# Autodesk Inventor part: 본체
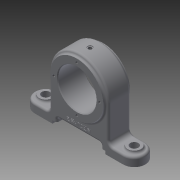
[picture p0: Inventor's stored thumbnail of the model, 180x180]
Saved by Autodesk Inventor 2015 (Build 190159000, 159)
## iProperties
Created: 2019-05
Part Number: 본체
Material: 알루미늄 6061
Document SubType Name: Modeling
Designer: now
Density: 2.7 g/cm^3
Appearance: 기본값
Mass: 455.028 g
Surface Area: 318.707 cm^2
Volume: 168.529 cm^3
Author: now
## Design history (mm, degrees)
sketch "스케치1"
  geometry: L1 (-75, 15)-(75, 15); L2 (75, 15)-(75, -15); L3 (75, -15)-(-75, -15); L4 (-75, -15)-(-75, 15); L5 (-75, 15)-(75, -15); L6 (75, 15)-(-75, -15); 1 further point
  constraints: 12 end point, 2 midpoint, 2 parallel, 1 horizontal, 1 perpendicular
  dimensions: "d0" = 150 distance of L2.end L3.end; "d1" = 30 distance of L1.end L2.end
extrude "돌출1" new body sketch "스케치1" distance "d2" = 12; taper "d3" = 0 deg
fillet "모깎기1" dims "d4" = 15
sketch "스케치2"
  geometry: L1 (120, 0)-(0, 0) reference; C1 r 40 at (60, 60); 2 further points
  constraints: 1 centre point, 1 midpoint, 1 vertical alignment
  dimensions: "d5" = 80 diameter of C1; "d6" = 60 distance of C1.centre point (60, 0)
extrude "돌출2" join sketch "스케치2" distance "d7" = 30; taper "d8" = 0 deg
sketch "스케치3"
  geometry: L1 (120, 0)-(0, 0) reference; L2 (0, 12)-(120, 12) reference; L3 (20, 12)-(100, 12); L4 (100, 12)-(100, 60); L5 (100, 60)-(20, 60); L6 (20, 60)-(20, 12); 3 further points
  constraints: 8 end point, 2 midpoint, 2 parallel, 1 horizontal, 1 perpendicular, 1 point on line, 1 vertical alignment
  dimensions: "d9" = 80 distance of L4.end L5.end; "d10" = 48 distance of L3.end L4.end
extrude "돌출3" join sketch "스케치3" distance "d11" = 30; taper "d12" = 0 deg
sketch "스케치4"
  geometry: A1 r 40 centre (60, 60) between (100, 60) and (20, 60) reference; 1 further point
hole "구멍1" sketch "스케치4" at (60, 60) diameter "d13" = 52; stored, may be unused: countersink angle "d17" = 90 deg, drill point angle "d19" = 118 deg; dims "d14" = 6, "d15" = 4, "d16" = 2, "d18" = 8
sketch "스케치5"
  geometry: C1 r 26 at (60, 60) reference; C2 r 36 at (60, 60); A1 r 40 centre (60, 60) between (100, 60) and (20, 60) reference; 1 further point
  constraints: 1 centre point, 1 coincident
  dimensions: "d20" = 72 diameter of C2
extrude "돌출4" join sketch "스케치5" distance "d21" = 3; taper "d22" = 0 deg
sketch "스케치6"
  geometry: C1 r 26 at (0, 0) reference; 2 further points
  constraints: 1 vertical alignment
  dimensions: "d23" = 31 distance of point (0, 31) C1.centre
hole "구멍2" sketch "스케치6" at (0, 31) diameter "d24" = 3.242; stored, may be unused: countersink angle "d28" = 90 deg, drill point angle "d30" = 118 deg; dims "d25" = 6, "d26" = 4, "d27" = 2, "d29" = 8
sketch "스케치7"
  geometry: C1 r 9 at (60, 0); A1 r 15 centre (60, 0) between (60, -15) and (60, 15) reference; 1 further point
  constraints: 1 centre point, 1 coincident
  dimensions: "d34" = 18 diameter of C1
extrude "돌출5" join sketch "스케치7" distance "d35" = 3; taper "d36" = 0 deg
sketch "스케치8"
  geometry: C1 r 9 at (0, 0) reference; 1 further point
hole "구멍3" sketch "스케치8" at (0, 0) diameter "d37" = 11; stored, may be unused: countersink angle "d41" = 90 deg, drill point angle "d43" = 118 deg; dims "d38" = 6, "d39" = 4, "d40" = 2, "d42" = 8
sketch "스케치9"
  geometry: L1 (-36, -60)-(36, -60); L2 (36, -60)-(36, -56); L3 (36, -56)-(-36, -56); L4 (-36, -56)-(-36, -60); 2 further points
  constraints: 8 end point, 2 parallel, 1 coincident, 1 horizontal, 1 midpoint, 1 perpendicular
  dimensions: "d44" = 72 distance of L1.start L1.end; "d45" = 4 distance of L1.end L2.end
extrude "돌출6" cut sketch "스케치9" stored distance "d46" = 3; taper "d47" = 0 deg
sketch "스케치11"
  geometry: L1 (-90, 0)-(-30, 0); L2 (-30, 0)-(-30, 10); L3 (-30, 10)-(-90, 10); L4 (-90, 10)-(-90, 0); 2 further points
  constraints: 8 end point, 2 parallel, 1 coincident, 1 horizontal, 1 midpoint, 1 perpendicular
  dimensions: "d52" = 60 distance of L1.start L1.end; "d53" = 10 distance of L1.end L2.end
extrude "돌출8" cut sketch "스케치11" stored distance "d54" = 3; taper "d55" = 0 deg
node "작업 평면1"
sketch "스케치13"
  geometry: 1 further point
hole "구멍4" sketch "스케치13" at (0, 0) diameter "d60" = 2; stored, may be unused: countersink angle "d64" = 90 deg, drill point angle "d66" = 118 deg; dims "d61" = 6, "d62" = 6, "d63" = 2, "d65" = 40
sketch "스케치14"
  geometry: 1 further point
hole "구멍5" sketch "스케치14" at (0, 0) diameter "d67" = 4.917; stored, may be unused: countersink angle "d71" = 90 deg, drill point angle "d73" = 118 deg; dims "d68" = 8, "d69" = 7, "d70" = 1, "d72" = 10
sketch "스케치15"
  geometry: C1 r 1.5 at (0, 26); 2 further points
  constraints: 2 vertical alignment, 1 centre point, 1 other
  dimensions: "d74" = 3 diameter of C1
extrude "돌출10" cut sketch "스케치15" stored distance "d75" = 1; taper "d76" = 0 deg
fillet "모깎기2" dims "d77" = 6
fillet "모깎기3" dims "d78" = 3
fillet "모깎기4" dims "d79" = 3
fillet "모깎기5" dims "d80" = 3
fillet "모깎기6" dims "d81" = 3
chamfer "모따기1" distance "d82" = 1; stored, may be unused: second distance "d83" = 2, angle "d84" = 45 deg
sketch "스케치16"
  geometry: L1 (33, 10)-(87, 10) reference; A1 r 39 centre (60, 60) between (23, 47.671) and (97, 47.671) reference; 2 further points
  constraints: 1 vertical alignment, 1 other
  dimensions: "d85" = 7 distance from line of point (60, 17) L1
feature "엠보싱1" sketch "스케치16" dims "d0" = 150, "d1" = 30, "d86" = 0.5, "d87" = 0
node "솔리드1"
mirror "대칭1"
pattern_circular "원형 패턴1" dims angle "d32" = 360 deg
mirror "대칭2"
mirror "대칭3"
